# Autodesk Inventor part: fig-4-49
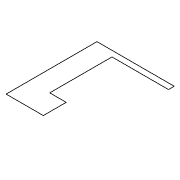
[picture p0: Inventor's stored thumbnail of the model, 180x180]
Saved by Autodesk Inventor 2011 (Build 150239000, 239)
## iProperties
Created: 2004-05
Part Number: fig-4-49
Document SubType Name: Modeling
Designer: CADCIM Technologies
Manufacturer: Standard
Standards Organization: Custom
Density: 1 g/cm^3
Author: CADCIM Technologies
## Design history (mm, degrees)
sketch "Sketch1"
  geometry: L1 (37.08, 12.209)-(23.643, 12.209); L2 (23.643, 12.209)-(23.643, 45.026); L3 (23.643, 45.026)-(51.55, 45.026); L4 (51.55, 45.026)-(51.55, 42.959); L5 (51.55, 42.959)-(31.137, 42.959); L6 (31.137, 42.959)-(31.137, 20.478); L7 (31.137, 20.478)-(37.08, 20.478); L8 (37.08, 20.478)-(37.08, 12.209)
  constraints: 16 end point, 6 parallel, 1 horizontal, 1 perpendicular, 1 other
